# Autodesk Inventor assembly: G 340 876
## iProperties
Company: Mayer & Müller AG
Created: 2006-06
Part Number: G 340 876
Document SubType Name: Assembly
Designer: I.Baliuc
Description: Leitblechanschluss
Mass: 331.204 g
Surface Area: 532.81 cm^2
Volume: 91.4904 cm^3
Density: 3.6201 g/cm^3
Zweck: Vorkontakt - HSLT
Author: T.Messerschmitt
Revision Number: 340876
